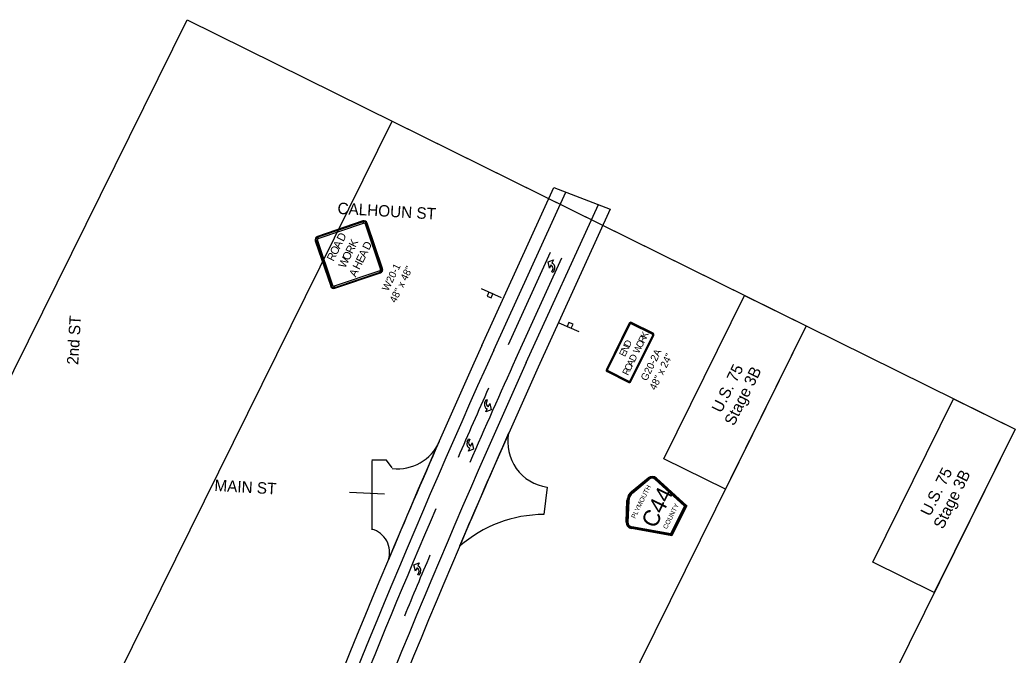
# Model space of a CAD drawing. Extents: x 14104283 to 14120882, y 8635219 to 8671666.
# Drawn here: x 14119794 to 14120882, y 8670971 to 8671666 of the extents above; entities that cross this region are included whole.
import ezdxf

# ---------------------------------------------------------------- set-up
doc = ezdxf.new("R2010")
doc.units = 0
for name, color, linetype in [('Cell', 7, 'Continuous'), ('Default', 7, 'Continuous'), ('dsnNonPlotable', 7, 'Continuous'), ('dsnPaintExistingBrokenLaneLineWhite', 7, 'Continuous'), ('dsnPaintExistingDoubleCenterYellow', 7, 'Continuous'), ('dsnPaintExistingLaneLineWhite', 7, 'Continuous'), ('dsnPaintExistingNoPassingYellow', 7, 'Continuous'), ('dsnPaintExistingSymbolWhite', 7, 'Continuous'), ('dsnTextOverlapEven', 7, 'Continuous'), ('Sign', 7, 'Continuous')]:
    doc.layers.add(name, color=color, linetype=linetype)

msp = doc.modelspace()

# ---------------------------------------------------------------- linework, layer by layer
at = {"layer": 'Cell'}
for p, q in [((14120168.9, 8671445.8), (14120119.2, 8671429)), ((14120169.2, 8671444.9), (14120169.7, 8671443.4)), ((14120171.3, 8671442.7), (14120172.8, 8671443.2)), ((14120190.5, 8671393.7), (14120173.7, 8671443.5)), ((14120116.8, 8671424.2), (14120133.7, 8671374.5)), ((14120117.7, 8671424.5), (14120119.2, 8671425)), ((14120120, 8671426.6), (14120119.5, 8671428.1)), ((14120375.7, 8671399.8), (14120375.9, 8671399.7)), ((14120138.4, 8671372.2), (14120188.1, 8671389)), ((14120187.3, 8671391.3), (14120187.8, 8671389.9)), ((14120189.6, 8671393.4), (14120188.1, 8671392.9)), ((14120374.9, 8671397.3), (14120374.6, 8671397.4)), ((14120136, 8671375.3), (14120134.6, 8671374.8)), ((14120138.1, 8671373), (14120137.6, 8671374.5)), ((14120298.1, 8671372), (14120320.1, 8671362.2)), ((14120405.4, 8671324.5), (14120383.4, 8671334.2)), ((14120460.2, 8671333.9), (14120435.2, 8671283.5)), ((14120460.6, 8671333.7), (14120461.3, 8671333.3)), ((14120462.1, 8671333.6), (14120462.5, 8671334.3)), ((14120486.2, 8671323.1), (14120462.7, 8671334.7)), ((14120486, 8671322.7), (14120485.6, 8671322)), ((14120462.1, 8671270.2), (14120487, 8671320.6)), ((14120485.9, 8671321.2), (14120486.6, 8671320.8)), ((14120436.3, 8671282.9), (14120435.6, 8671283.3)), ((14120436.1, 8671281), (14120459.6, 8671269.3)), ((14120436.3, 8671281.4), (14120436.6, 8671282.1)), ((14120460.2, 8671270.4), (14120459.8, 8671269.7)), ((14120461.7, 8671270.4), (14120461, 8671270.7)), ((14120305, 8671240.3), (14120304.8, 8671240.4)), ((14120305.8, 8671242.8), (14120306.1, 8671242.7)), ((14120228.2, 8671066.1), (14120227.9, 8671066.2)), ((14120229, 8671068.6), (14120229.2, 8671068.5))]:
    msp.add_line(p, q, dxfattribs=at)
for points in [[(14120169.2, 8671444.9), (14120119.5, 8671428.1), (14120120, 8671426.6), (14120169.7, 8671443.4), (14120169.2, 8671444.9)], [(14120189.6, 8671393.4), (14120172.8, 8671443.2), (14120171.3, 8671442.7), (14120188.1, 8671392.9), (14120189.6, 8671393.4)], [(14120117.7, 8671424.5), (14120134.6, 8671374.8), (14120136, 8671375.3), (14120119.2, 8671425), (14120117.7, 8671424.5)], [(14120138.1, 8671373), (14120187.8, 8671389.9), (14120187.3, 8671391.3), (14120137.6, 8671374.5), (14120138.1, 8671373)], [(14120311.2, 8671366.1), (14120306.7, 8671368.1), (14120304.7, 8671363.6), (14120309.2, 8671361.6)], [(14120392.3, 8671330.4), (14120396.8, 8671328.4), (14120398.7, 8671332.9), (14120394.3, 8671334.9)], [(14120460.6, 8671333.7), (14120435.6, 8671283.3), (14120436.3, 8671282.9), (14120461.3, 8671333.3), (14120460.6, 8671333.7)], [(14120486, 8671322.7), (14120462.5, 8671334.3), (14120462.1, 8671333.6), (14120485.6, 8671322), (14120486, 8671322.7)], [(14120461.7, 8671270.4), (14120486.6, 8671320.8), (14120485.9, 8671321.2), (14120461, 8671270.7), (14120461.7, 8671270.4)], [(14120436.3, 8671281.4), (14120459.8, 8671269.7), (14120460.2, 8671270.4), (14120436.6, 8671282.1), (14120436.3, 8671281.4)]]:
    msp.add_lwpolyline(points, close=True, dxfattribs=at)
for points in [[(14120371.5, 8671401), (14120377.3, 8671403.2), (14120375.7, 8671399.8)], [(14120371.5, 8671401), (14120377.3, 8671403.2), (14120375.7, 8671399.8)], [(14120374.6, 8671397.4), (14120373, 8671394.1), (14120371.5, 8671401)], [(14120374.6, 8671397.4), (14120373, 8671394.1), (14120371.5, 8671401)], [(14120375.7, 8671399.8), (14120375.9, 8671399.7)], [(14120374.9, 8671397.3), (14120374.6, 8671397.4)], [(14120378.5, 8671393), (14120377.1, 8671389.6), (14120375.7, 8671390.2), (14120376.7, 8671392.6)], [(14120378.5, 8671393), (14120377.1, 8671389.6), (14120375.7, 8671390.2), (14120376.7, 8671392.6)], [(14120311.2, 8671366.1), (14120306.7, 8671368.1), (14120304.7, 8671363.6), (14120309.2, 8671361.6), (14120311.2, 8671366.1)], [(14120392.3, 8671330.4), (14120396.8, 8671328.4), (14120398.7, 8671332.9), (14120394.3, 8671334.9), (14120392.3, 8671330.4)], [(14120302.2, 8671247.1), (14120303.6, 8671250.5), (14120305, 8671250), (14120304, 8671247.5)], [(14120302.2, 8671247.1), (14120303.6, 8671250.5), (14120305, 8671250), (14120304, 8671247.5)], [(14120306.1, 8671242.7), (14120307.7, 8671246), (14120309.1, 8671239.2)], [(14120306.1, 8671242.7), (14120307.7, 8671246), (14120309.1, 8671239.2)], [(14120309.1, 8671239.2), (14120303.4, 8671237), (14120305, 8671240.3)], [(14120309.1, 8671239.2), (14120303.4, 8671237), (14120305, 8671240.3)], [(14120305, 8671240.3), (14120304.8, 8671240.4)], [(14120305.8, 8671242.8), (14120306.1, 8671242.7)], [(14120224.8, 8671069.7), (14120230.6, 8671071.9), (14120229, 8671068.6)], [(14120224.8, 8671069.7), (14120230.6, 8671071.9), (14120229, 8671068.6)], [(14120227.9, 8671066.2), (14120226.3, 8671062.9), (14120224.8, 8671069.7)], [(14120227.9, 8671066.2), (14120226.3, 8671062.9), (14120224.8, 8671069.7)], [(14120228.2, 8671066.1), (14120227.9, 8671066.2)], [(14120229, 8671068.6), (14120229.2, 8671068.5)], [(14120231.8, 8671061.8), (14120230.4, 8671058.4), (14120229, 8671058.9), (14120230, 8671061.4)], [(14120231.8, 8671061.8), (14120230.4, 8671058.4), (14120229, 8671058.9), (14120230, 8671061.4)]]:
    msp.add_lwpolyline(points, dxfattribs=at)
for centre, radius, start, end in [((14120170.1, 8671442.3), 3.75, 18.6913, 108.691), ((14120170.1, 8671442.3), 2.81, 18.6913, 108.691), ((14120170.1, 8671442.3), 1.25, 18.6913, 108.691), ((14120120.4, 8671425.4), 3.75, 108.6912, 198.6909), ((14120120.4, 8671425.4), 2.81, 108.6912, 198.6909), ((14120120.4, 8671425.4), 1.25, 108.6912, 198.6909), ((14120186.9, 8671392.5), 1.25, 288.6911, 18.6913), ((14120186.9, 8671392.5), 2.81, 288.6911, 18.6913), ((14120186.9, 8671392.5), 3.75, 288.6911, 18.6913), ((14120137.2, 8671375.7), 3.75, 198.6909, 288.6911), ((14120137.2, 8671375.7), 2.81, 198.6909, 288.6911), ((14120137.2, 8671375.7), 1.25, 198.6909, 288.6911), ((14120461.8, 8671333.1), 1.87, 63.6912, 153.6914), ((14120461.8, 8671333.1), 1.41, 63.6912, 153.6914), ((14120461.8, 8671333.1), 0.625, 63.6912, 153.6914), ((14120485.4, 8671321.4), 0.625, 333.6912, 63.6914), ((14120485.4, 8671321.4), 1.41, 333.6912, 63.6914), ((14120485.4, 8671321.4), 1.87, 333.6912, 63.6914), ((14120436.9, 8671282.6), 1.87, 153.6914, 243.691), ((14120436.9, 8671282.6), 1.41, 153.6914, 243.691), ((14120436.9, 8671282.6), 0.625, 153.6914, 243.691), ((14120460.4, 8671271), 1.87, 243.691, 333.6912), ((14120460.4, 8671271), 1.41, 243.691, 333.6912), ((14120460.4, 8671271), 0.625, 243.691, 333.6912)]:
    msp.add_arc(centre, radius, start, end, dxfattribs=at)
for centre, major_axis in [((14120373.9, 8671394.9), (-2, -4.86)), ((14120373.9, 8671394.9), (-2, -4.86)), ((14120373.5, 8671393.9), (-1.4, -3.4)), ((14120373.5, 8671393.9), (-1.4, -3.4)), ((14120306.8, 8671245.2), (2, 4.86)), ((14120306.8, 8671245.2), (2, 4.86)), ((14120307.2, 8671246.2), (1.4, 3.4)), ((14120307.2, 8671246.2), (1.4, 3.4)), ((14120226.8, 8671062.7), (-1.4, -3.4)), ((14120226.8, 8671062.7), (-1.4, -3.4)), ((14120227.2, 8671063.6), (-2, -4.86)), ((14120227.2, 8671063.6), (-2, -4.86))]:
    msp.add_ellipse(centre, major_axis=major_axis, ratio=0.9474, start_param=1.570796, end_param=3.141593, dxfattribs=at)
at = {"layer": 'Default'}
for p, q in [((14120299, 8671309.7), (14120377.9, 8671482.5)), ((14120377.9, 8671482.5), (14120439.4, 8671458.6)), ((14120439.4, 8671458.6), (14120360.6, 8671285.8)), ((14120178.7, 8671183.5), (14120178.6, 8671107.9)), ((14120178.7, 8671183.5), (14120178.6, 8671107.9)), ((14120194.8, 8671184.3), (14120178.7, 8671184.3)), ((14120194.8, 8671184.3), (14120178.7, 8671184.3)), ((14120201.1, 8671175.8), (14120194.8, 8671184.3)), ((14120201.1, 8671175.8), (14120194.8, 8671184.3)), ((14120370.3, 8671154.6), (14120366.9, 8671124.9)), ((14120370.3, 8671154.6), (14120366.9, 8671124.9))]:
    msp.add_line(p, q, dxfattribs=at)
for centre, radius, start, end in [((14129121.8, 8667322.2), 9682.1, 155.67905, 159.75253), ((14129183.4, 8667298.3), 9682.1, 155.67905, 159.75253), ((14129183.4, 8667298.3), 9682.1, 156.14717, 156.94403), ((14129183.4, 8667298.3), 9682.1, 156.14717, 156.94403), ((14120377.6, 8671204.3), 50.2, 169.2669, 261.6204), ((14120377.6, 8671204.3), 50.2, 169.2669, 261.6204), ((14129121.8, 8667321.8), 9682.1, 156.35706, 157.19061), ((14129121.8, 8667321.8), 9682.1, 156.35706, 157.19061), ((14120206.8, 8671224.6), 49.9, 263.4387, 336.3571), ((14120206.8, 8671224.6), 49.9, 263.4387, 336.3571), ((14120367.2, 8670984.5), 140.3, 90.1123, 131.2245), ((14120367.2, 8670984.5), 140.3, 90.1123, 131.2245), ((14120171.7, 8671083.2), 26.5, 342.4439, 74.5077), ((14120171.7, 8671083.2), 26.5, 342.4439, 74.5077)]:
    msp.add_arc(centre, radius, start, end, dxfattribs=at)
at = {"layer": 'dsnNonPlotable'}
for points in [[(14119282, 8670260.6), (14119976.8, 8671665.7), (14120882.2, 8671218.1), (14120187.4, 8669813)], [(14119506.2, 8670149.8), (14120200.9, 8671554.9), (14120653.6, 8671331.1), (14119958.8, 8669926)]]:
    msp.add_lwpolyline(points, close=True, dxfattribs=at)
at = {"layer": 'dsnPaintExistingBrokenLaneLineWhite'}
for p, q in [((14120312.1, 8671304.6), (14120390.9, 8671477.4)), ((14120347.5, 8671290.9), (14120426.4, 8671463.7))]:
    msp.add_line(p, q, dxfattribs=at)
for centre in [(14129134.9, 8667317.1), (14129170.3, 8667303.4)]:
    msp.add_arc(centre, 9682.1, 155.67905, 159.75253, dxfattribs=at)
at = {"layer": 'dsnPaintExistingDoubleCenterYellow'}
msp.add_line((14120154.2, 8671149.1), (14120192.4, 8671147.3), dxfattribs=at)
at = {"layer": 'dsnPaintExistingLaneLineWhite'}
for centre, start, end in [((14129146.1, 8667312.8), 155.92282, 156.41213), ((14129159.1, 8667307.7), 157.06665, 157.496)]:
    msp.add_arc(centre, 9682.1, start, end, dxfattribs=at)
at = {"layer": 'dsnPaintExistingNoPassingYellow'}
for p, q in [((14120373.9, 8671411.3), (14120327.8, 8671310.2)), ((14120336.3, 8671295.2), (14120386.6, 8671405.5))]:
    msp.add_line(p, q, dxfattribs=at)
for centre, start, end in [((14129159.1, 8667307.7), 155.67905, 156.4156), ((14129146.1, 8667312.8), 156.77428, 159.75253)]:
    msp.add_arc(centre, 9682.1, start, end, dxfattribs=at)
at = {"layer": 'dsnPaintExistingSymbolWhite'}
for p, q in [((14120375.7, 8671399.8), (14120375.9, 8671399.7)), ((14120374.9, 8671397.3), (14120374.6, 8671397.4)), ((14120305, 8671240.3), (14120304.8, 8671240.4)), ((14120305.8, 8671242.8), (14120306.1, 8671242.7)), ((14120285.9, 8671197.3), (14120285.7, 8671197.4)), ((14120286.7, 8671199.8), (14120287, 8671199.7)), ((14120228.2, 8671066.1), (14120227.9, 8671066.2)), ((14120229, 8671068.6), (14120229.2, 8671068.5))]:
    msp.add_line(p, q, dxfattribs=at)
for points in [[(14120371.5, 8671401), (14120377.3, 8671403.2), (14120375.7, 8671399.8)], [(14120371.5, 8671401), (14120377.3, 8671403.2), (14120375.7, 8671399.8)], [(14120374.6, 8671397.4), (14120373, 8671394.1), (14120371.5, 8671401)], [(14120374.6, 8671397.4), (14120373, 8671394.1), (14120371.5, 8671401)], [(14120375.7, 8671399.8), (14120375.9, 8671399.7)], [(14120374.9, 8671397.3), (14120374.6, 8671397.4)], [(14120378.5, 8671393), (14120377.1, 8671389.6), (14120375.7, 8671390.2), (14120376.7, 8671392.6)], [(14120378.5, 8671393), (14120377.1, 8671389.6), (14120375.7, 8671390.2), (14120376.7, 8671392.6)], [(14120302.2, 8671247.1), (14120303.6, 8671250.5), (14120305, 8671250), (14120304, 8671247.5)], [(14120302.2, 8671247.1), (14120303.6, 8671250.5), (14120305, 8671250), (14120304, 8671247.5)], [(14120306.1, 8671242.7), (14120307.7, 8671246), (14120309.1, 8671239.2)], [(14120306.1, 8671242.7), (14120307.7, 8671246), (14120309.1, 8671239.2)], [(14120309.1, 8671239.2), (14120303.4, 8671237), (14120305, 8671240.3)], [(14120309.1, 8671239.2), (14120303.4, 8671237), (14120305, 8671240.3)], [(14120305, 8671240.3), (14120304.8, 8671240.4)], [(14120305.8, 8671242.8), (14120306.1, 8671242.7)], [(14120283.1, 8671204.2), (14120284.5, 8671207.6), (14120285.9, 8671207), (14120284.9, 8671204.6)], [(14120283.1, 8671204.2), (14120284.5, 8671207.6), (14120285.9, 8671207), (14120284.9, 8671204.6)], [(14120287, 8671199.7), (14120288.6, 8671203), (14120290, 8671196.2)], [(14120287, 8671199.7), (14120288.6, 8671203), (14120290, 8671196.2)], [(14120290, 8671196.2), (14120284.3, 8671194), (14120285.9, 8671197.3)], [(14120290, 8671196.2), (14120284.3, 8671194), (14120285.9, 8671197.3)], [(14120285.9, 8671197.3), (14120285.7, 8671197.4)], [(14120286.7, 8671199.8), (14120287, 8671199.7)], [(14120224.8, 8671069.7), (14120230.6, 8671071.9), (14120229, 8671068.6)], [(14120224.8, 8671069.7), (14120230.6, 8671071.9), (14120229, 8671068.6)], [(14120227.9, 8671066.2), (14120226.3, 8671062.9), (14120224.8, 8671069.7)], [(14120227.9, 8671066.2), (14120226.3, 8671062.9), (14120224.8, 8671069.7)], [(14120228.2, 8671066.1), (14120227.9, 8671066.2)], [(14120229, 8671068.6), (14120229.2, 8671068.5)], [(14120231.8, 8671061.8), (14120230.4, 8671058.4), (14120229, 8671058.9), (14120230, 8671061.4)], [(14120231.8, 8671061.8), (14120230.4, 8671058.4), (14120229, 8671058.9), (14120230, 8671061.4)]]:
    msp.add_lwpolyline(points, dxfattribs=at)
for centre, major_axis in [((14120373.9, 8671394.9), (-2, -4.86)), ((14120373.9, 8671394.9), (-2, -4.86)), ((14120373.5, 8671393.9), (-1.4, -3.4)), ((14120373.5, 8671393.9), (-1.4, -3.4)), ((14120306.8, 8671245.2), (2, 4.86)), ((14120306.8, 8671245.2), (2, 4.86)), ((14120307.2, 8671246.2), (1.4, 3.4)), ((14120307.2, 8671246.2), (1.4, 3.4)), ((14120287.7, 8671202.3), (2, 4.86)), ((14120287.7, 8671202.3), (2, 4.86)), ((14120288.1, 8671203.2), (1.4, 3.4)), ((14120288.1, 8671203.2), (1.4, 3.4)), ((14120226.8, 8671062.7), (-1.4, -3.4)), ((14120226.8, 8671062.7), (-1.4, -3.4)), ((14120227.2, 8671063.6), (-2, -4.86)), ((14120227.2, 8671063.6), (-2, -4.86))]:
    msp.add_ellipse(centre, major_axis=major_axis, ratio=0.9474, start_param=1.570796, end_param=3.141593, dxfattribs=at)
at = {"layer": 'dsnTextOverlapEven'}
for points in [[(14120653.6, 8671331.1), (14120565.3, 8671152.5), (14120498, 8671185.7), (14120586.3, 8671364.3)], [(14120498, 8671185.7), (14120586.3, 8671364.3), (14120653.6, 8671331.1), (14120565.3, 8671152.5)], [(14120882.2, 8671218.1), (14120793.8, 8671039.4), (14120726.6, 8671072.7), (14120814.9, 8671251.3)], [(14120726.6, 8671072.7), (14120814.9, 8671251.3), (14120882.2, 8671218.1), (14120793.8, 8671039.4)]]:
    msp.add_lwpolyline(points, close=True, dxfattribs=at)
at = {"layer": 'Sign'}
for p, q in [((14120462.7, 8671150), (14120480.8, 8671164.9)), ((14120481.4, 8671164.1), (14120463.3, 8671149.3)), ((14120463.3, 8671149.3), (14120481.4, 8671164.1)), ((14120464, 8671148.5), (14120482, 8671163.4)), ((14120482, 8671163.4), (14120464, 8671148.5)), ((14120488.6, 8671163.2), (14120520.7, 8671133.9)), ((14120520.7, 8671133.9), (14120488.6, 8671163.2)), ((14120521.9, 8671134.2), (14120489.3, 8671163.9)), ((14120489.3, 8671163.9), (14120521.9, 8671134.2)), ((14120489.9, 8671164.6), (14120523, 8671134.4)), ((14120456.9, 8671116.5), (14120457.7, 8671139.9)), ((14120458.7, 8671139.8), (14120457.8, 8671116.4)), ((14120457.8, 8671116.4), (14120458.7, 8671139.8)), ((14120458.8, 8671116.4), (14120459.7, 8671139.8)), ((14120459.7, 8671139.8), (14120458.8, 8671116.4)), ((14120520.7, 8671133.9), (14120505.7, 8671103.6)), ((14120505.7, 8671103.6), (14120520.7, 8671133.9)), ((14120506.2, 8671102.5), (14120521.9, 8671134.2)), ((14120521.9, 8671134.2), (14120506.2, 8671102.5)), ((14120523, 8671134.4), (14120506.7, 8671101.4)), ((14120523, 8671134.4), (14120521.9, 8671134.2)), ((14120506.7, 8671101.4), (14120462.6, 8671109.4)), ((14120462.8, 8671110.3), (14120506.2, 8671102.5)), ((14120506.2, 8671102.5), (14120462.8, 8671110.3)), ((14120505.7, 8671103.6), (14120462.9, 8671111.3)), ((14120462.9, 8671111.3), (14120505.7, 8671103.6)), ((14120505.7, 8671103.6), (14120506.2, 8671102.5))]:
    msp.add_line(p, q, dxfattribs=at)
for centre, radius, start, end in [((14120485.2, 8671159.5), 6.97, 47.5883, 129.4611), ((14120485.2, 8671159.5), 5.99, 47.5883, 129.4611), ((14120485.2, 8671159.5), 5.99, 47.5883, 129.4611), ((14120485.2, 8671159.5), 5.02, 47.5883, 129.4611), ((14120485.2, 8671159.5), 5.02, 47.5883, 129.4611), ((14120471.5, 8671139.4), 13.8, 129.4611, 177.9213), ((14120471.5, 8671139.4), 12.8, 129.4611, 177.9213), ((14120471.5, 8671139.4), 12.8, 129.4611, 177.9213), ((14120471.5, 8671139.4), 11.8, 129.4611, 177.9213), ((14120471.5, 8671139.4), 11.8, 129.4611, 177.9213), ((14120463.8, 8671116.2), 6.97, 177.9213, 259.7941), ((14120463.8, 8671116.2), 5.99, 177.9213, 259.7941), ((14120463.8, 8671116.2), 5.99, 177.9213, 259.7941), ((14120463.8, 8671116.2), 5.02, 177.9213, 259.7941), ((14120463.8, 8671116.2), 5.02, 177.9213, 259.7941)]:
    msp.add_arc(centre, radius, start, end, dxfattribs=at)

# ---------------------------------------------------------------- texts
at = {"layer": 'Cell'}
for s, height, p in [('D', 8.75, (14120147.6, 8671422.7)), ('A', 8.75, (14120143.6, 8671414.7)), ('K', 8.75, (14120160.8, 8671416.3)), ('D', 8.75, (14120175.6, 8671413.2)), ('R', 8.75, (14120136.8, 8671401)), ('O', 8.75, (14120140.2, 8671407.8)), ('O', 8.75, (14120153.6, 8671401.8)), ('R', 8.75, (14120157.3, 8671409.2)), ('E', 8.75, (14120168.7, 8671399.2)), ('A', 8.75, (14120171.6, 8671405)), ('W', 8.75, (14120149.5, 8671393.5)), ('H', 8.75, (14120165.1, 8671391.9)), ('W20-1', 8, (14120196.5, 8671368.4)), ('A', 8.75, (14120161.1, 8671383.7)), ('48" x 48"', 8, (14120204.7, 8671355.6)), ('K', 7.5, (14120478.8, 8671316.6)), ('D', 7.5, (14120460.4, 8671306.9)), ('W', 7.5, (14120470.6, 8671300.1)), ('O', 7.5, (14120473.7, 8671306.3)), ('R', 7.5, (14120476.3, 8671311.6)), ('E', 7.5, (14120455.4, 8671296.7)), ('N', 7.5, (14120457.7, 8671301.5)), ('G20-2A', 8, (14120479.4, 8671270.2)), ('48" x 24"', 8, (14120488.9, 8671260.1)), ('O', 7.5, (14120461.2, 8671281.1)), ('A', 7.5, (14120463.7, 8671286.1)), ('D', 7.5, (14120466.3, 8671291.4)), ('R', 7.5, (14120458.9, 8671276.3))]:
    msp.add_text(s, height=height, rotation=63.6912, dxfattribs=at).set_placement(p)
at = {"layer": 'dsnTextOverlapEven'}
for s, rotation, p in [('CALHOUN ST', 356.6912, (14120140.9, 8671453.6)), ('2nd ST', 86.6912, (14119857.6, 8671288.2)), ('U.S. 75', 63.6912, (14120560.8, 8671235.1)), ('Stage 3B', 63.6912, (14120574.7, 8671220.9)), ('U.S. 75', 63.6912, (14120789.3, 8671122)), ('Stage 3B', 63.6912, (14120803.3, 8671107.9)), ('MAIN ST', 356.6912, (14120006.3, 8671150.6))]:
    msp.add_text(s, height=12.5, rotation=rotation, dxfattribs=at).set_placement(p)
at = {"layer": 'Sign'}
for s, height, p in [('PLYMOUTH', 5.18, (14120466.6, 8671119.8)), ('C44', 18.14, (14120488.9, 8671108.7)), ('COUNTY', 5.18, (14120501.4, 8671108.3))]:
    msp.add_text(s, height=height, rotation=63.6912, dxfattribs=at).set_placement(p)

doc.saveas('drawing.dxf')
